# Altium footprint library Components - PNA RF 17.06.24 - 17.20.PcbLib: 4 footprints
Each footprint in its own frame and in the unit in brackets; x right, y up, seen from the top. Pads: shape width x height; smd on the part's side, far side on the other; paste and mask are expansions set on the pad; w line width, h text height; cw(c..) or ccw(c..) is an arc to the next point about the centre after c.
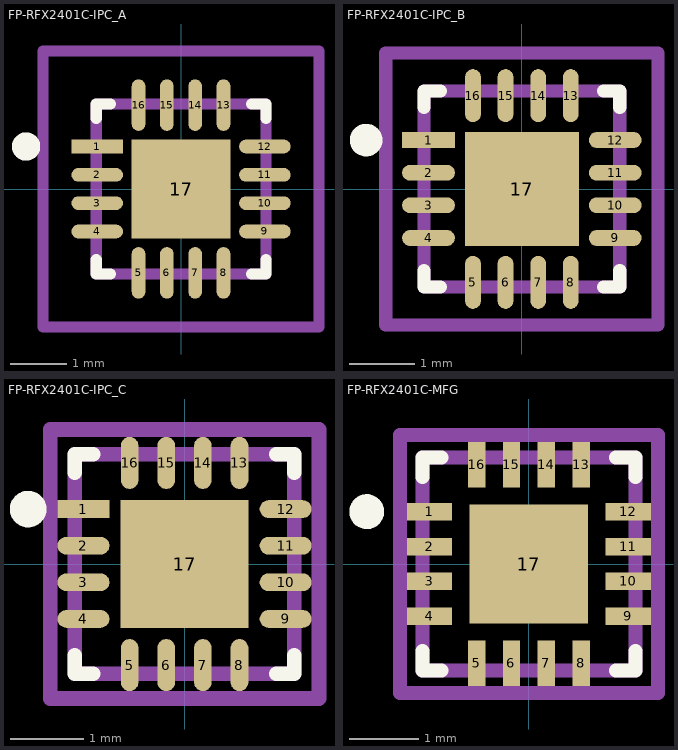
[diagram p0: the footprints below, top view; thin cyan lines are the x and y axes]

## FP-RFX2401C-IPC_A [mm]
pads (17):
  rect 0.911x0.242 smd paste+0 mask+0: 1(-1.481,0.75)
  rrect100% 0.911x0.242 smd paste+0 mask+0: 2(-1.481,0.25) 3(-1.481,-0.25) 4(-1.481,-0.75) 9(1.481,-0.75) 10(1.481,-0.25) 11(1.481,0.25) 12(1.481,0.75)
  rrect100% 0.242x0.911 smd paste+0 mask+0: 5(-0.75,-1.481) 6(-0.25,-1.481) 7(0.25,-1.481) 8(0.75,-1.481) 13(0.75,1.481) 14(0.25,1.481) 15(-0.25,1.481) 16(-0.75,1.481)
  rect 1.75x1.75 smd paste-1000 mask+0: 17(0,0)
Top Overlay:
  circle w0.25: c-2.736,0.75 r0.125
  lines w0.2: -1.5,-1.25 -1.5,-1.5 -1.25,-1.5 ; -1.5,1.25 -1.5,1.5 -1.25,1.5 ; 1.25,-1.5 1.5,-1.5 1.5,-1.25 ; 1.25,1.5 1.5,1.5 1.5,1.25
Top Paste:
  rectangle: -0.553,-0.553 0.553,0.553
Top Assembly:
  lines w0.2: -2.436,-2.436 2.436,-2.436 2.436,2.436 -2.436,2.436 -2.436,-2.436
  text ".Designator" at 0,0.188 h1
Top 3D Body:
  lines w0.2: -1.5,-1.5 1.5,-1.5 1.5,1.5 -1.5,1.5 -1.5,-1.5
Top Courtyard:
  lines w0.2: -2.436,-2.436 2.436,-2.436 2.436,2.436 -2.436,2.436 -2.436,-2.436
Top Component Center:
  lines w0.1: -0.5,0 0.5,0 ; 0,-0.5 0,0.5
3D body "IC_Skyworks_Solutions_RFX2401C_eec.STEP": height 0.25, standoff 0, extent -2.436,-2.436 2.436,2.436

## FP-RFX2401C-IPC_B [mm]
pads (17):
  rect 0.811x0.242 smd paste+0 mask+0: 1(-1.431,0.75)
  rrect100% 0.811x0.242 smd paste+0 mask+0: 2(-1.431,0.25) 3(-1.431,-0.25) 4(-1.431,-0.75) 9(1.431,-0.75) 10(1.431,-0.25) 11(1.431,0.25) 12(1.431,0.75)
  rrect100% 0.242x0.811 smd paste+0 mask+0: 5(-0.75,-1.431) 6(-0.25,-1.431) 7(0.25,-1.431) 8(0.75,-1.431) 13(0.75,1.431) 14(0.25,1.431) 15(-0.25,1.431) 16(-0.75,1.431)
  rect 1.75x1.75 smd paste-1000 mask+0: 17(0,0)
Top Overlay:
  circle w0.25: c-2.386,0.75 r0.125
  lines w0.2: -1.5,-1.25 -1.5,-1.5 -1.25,-1.5 ; -1.5,1.25 -1.5,1.5 -1.25,1.5 ; 1.25,-1.5 1.5,-1.5 1.5,-1.25 ; 1.25,1.5 1.5,1.5 1.5,1.25
Top Paste:
  rectangle: -0.553,-0.553 0.553,0.553
Top Assembly:
  lines w0.2: -2.086,-2.086 2.086,-2.086 2.086,2.086 -2.086,2.086 -2.086,-2.086
  text ".Designator" at 0,0.188 h1
Top 3D Body:
  lines w0.2: -1.5,-1.5 1.5,-1.5 1.5,1.5 -1.5,1.5 -1.5,-1.5
Top Courtyard:
  lines w0.2: -2.086,-2.086 2.086,-2.086 2.086,2.086 -2.086,2.086 -2.086,-2.086
Top Component Center:
  lines w0.1: -0.5,0 0.5,0 ; 0,-0.5 0,0.5
3D body "IC_Skyworks_Solutions_RFX2401C_eec.STEP": height 0.25, standoff 0, extent -2.086,-2.086 2.086,2.086

## FP-RFX2401C-IPC_C [mm]
pads (17):
  rect 0.711x0.242 smd paste+0 mask+0: 1(-1.381,0.75)
  rrect100% 0.711x0.242 smd paste+0 mask+0: 2(-1.381,0.25) 3(-1.381,-0.25) 4(-1.381,-0.75) 9(1.381,-0.75) 10(1.381,-0.25) 11(1.381,0.25) 12(1.381,0.75)
  rrect100% 0.242x0.711 smd paste+0 mask+0: 5(-0.75,-1.381) 6(-0.25,-1.381) 7(0.25,-1.381) 8(0.75,-1.381) 13(0.75,1.381) 14(0.25,1.381) 15(-0.25,1.381) 16(-0.75,1.381)
  rect 1.75x1.75 smd paste-1000 mask+0: 17(0,0)
Top Overlay:
  circle w0.25: c-2.136,0.75 r0.125
  lines w0.2: -1.5,-1.25 -1.5,-1.5 -1.25,-1.5 ; -1.5,1.25 -1.5,1.5 -1.25,1.5 ; 1.25,-1.5 1.5,-1.5 1.5,-1.25 ; 1.25,1.5 1.5,1.5 1.5,1.25
Top Paste:
  rectangle: -0.553,-0.553 0.553,0.553
Top Assembly:
  lines w0.2: -1.836,-1.836 1.836,-1.836 1.836,1.836 -1.836,1.836 -1.836,-1.836
  text ".Designator" at 0,0.188 h1
Top 3D Body:
  lines w0.2: -1.5,-1.5 1.5,-1.5 1.5,1.5 -1.5,1.5 -1.5,-1.5
Top Courtyard:
  lines w0.2: -1.836,-1.836 1.836,-1.836 1.836,1.836 -1.836,1.836 -1.836,-1.836
Top Component Center:
  lines w0.1: -0.5,0 0.5,0 ; 0,-0.5 0,0.5
3D body "IC_Skyworks_Solutions_RFX2401C_eec.STEP": height 0.25, standoff 0, extent -1.836,-1.836 1.836,1.836

## FP-RFX2401C-MFG [mm]
pads (17):
  rect 0.65x0.25 smd paste+0 mask+0: 1(-1.425,0.75) 2(-1.425,0.25) 3(-1.425,-0.25) 4(-1.425,-0.75) 9(1.425,-0.75) 10(1.425,-0.25) 11(1.425,0.25) 12(1.425,0.75)
  rect 0.25x0.65 smd paste+0 mask+0: 5(-0.75,-1.425) 6(-0.25,-1.425) 7(0.25,-1.425) 8(0.75,-1.425) 13(0.75,1.425) 14(0.25,1.425) 15(-0.25,1.425) 16(-0.75,1.425)
  rect 1.7x1.7 smd paste+0 mask+0: 17(0,0)
Top Overlay:
  circle w0.25: c-2.325,0.75 r0.125
  lines w0.2: -1.525,-1.25 -1.525,-1.525 -1.25,-1.525 ; -1.525,1.25 -1.525,1.525 -1.25,1.525 ; 1.25,-1.525 1.525,-1.525 1.525,-1.25 ; 1.25,1.525 1.525,1.525 1.525,1.25
Top Assembly:
  lines w0.2: -1.85,-1.85 1.85,-1.85 1.85,1.85 -1.85,1.85 -1.85,-1.85
  text ".Designator" at 0,0.188 h1
Top 3D Body:
  lines w0.2: -1.525,-1.525 1.525,-1.525 1.525,1.525 -1.525,1.525 -1.525,-1.525
Top Courtyard:
  lines w0.2: -1.85,-1.85 1.85,-1.85 1.85,1.85 -1.85,1.85 -1.85,-1.85
Top Component Center:
  lines w0.1: -0.5,0 0.5,0 ; 0,-0.5 0,0.5
3D body "IC_Skyworks_Solutions_RFX2401C_eec.STEP": height 0.25, standoff 0, extent -1.85,-1.85 1.85,1.85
